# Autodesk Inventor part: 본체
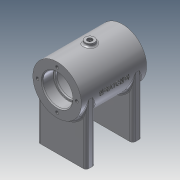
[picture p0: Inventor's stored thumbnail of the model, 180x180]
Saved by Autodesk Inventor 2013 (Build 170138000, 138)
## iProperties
Created: 2020-07
Part Number: 본체
Material: 알루미늄 6061
Document SubType Name: Modeling
Designer: user
Mass: 305.001 g
Surface Area: 360.073 cm^2
Volume: 112.546 cm^3
Density: 2.71 g/cm^3
Author: user
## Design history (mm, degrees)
sketch "스케치1"
  geometry: C1 r 26 at (0, 0); 1 further point
  constraints: 1 centre point, 1 coincident
  dimensions: "d0" = 52 diameter of C1
extrude "돌출1" new body sketch "스케치1" stored distance "d1" = 70; taper "d2" = 0 deg
node "작업 평면1"
sketch "스케치2"
  geometry: L1 (26, 30)-(-26, 30); L2 (-26, 30)-(-26, 20); L3 (-26, 20)-(26, 20); L4 (26, 20)-(26, 30); L5 (26, -20)-(-26, -20); L6 (-26, -20)-(-26, -30); L7 (-26, -30)-(26, -30); L8 (26, -30)-(26, -20); L9 (15, 0)-(-15, 0); 4 further points
  constraints: 18 end point, 4 parallel, 3 midpoint, 3 perpendicular, 2 horizontal, 2 vertical alignment, 1 coincident, 1 other
  dimensions: "d4" = 60 distance between parallel lines of L7 L1; "d6" = 52 distance between parallel lines of L2 L4; "d7" = 10 distance of L1.end L2.end; "d8" = 10 distance of L5.end L6.end; "d9" = 52 distance of L6.end L7.end; "d10" = 30 distance of L9.start L9.end
extrude "돌출2" join sketch "스케치2" stored distance "d11" = 70; taper "d12" = 0 deg
sketch "스케치3"
  geometry: C1 r 26 at (0, 0) reference; C2 r 16 at (0, 0)
  constraints: 1 centre point, 1 coincident
  dimensions: "d13" = 32 diameter of C2
extrude "돌출3" cut sketch "스케치3" distance "d14" = 12; taper "d15" = 0 deg
sketch "스케치4"
  geometry: C1 r 16 at (0, 0) reference; C2 r 14 at (0, 0)
  constraints: 1 centre point, 1 coincident
  dimensions: "d16" = 28 diameter of C2
extrude "돌출4" cut sketch "스케치4" distance "d17" = 2; taper "d18" = 0 deg
sketch "스케치5"
  geometry: C1 r 14 at (0, 0) reference; C2 r 21 at (0, 0)
  constraints: 1 centre point, 1 coincident
  dimensions: "d19" = 42 diameter of C2
extrude "돌출5" cut sketch "스케치5" distance "d20" = 42; taper "d21" = 0 deg
node "작업 평면2"
sketch "스케치6"
  geometry: L1 (0, 0)-(0, -26); L2 (7.182, -19.734)-(9.919, -27.251); L3 (9.919, -27.251)-(15.557, -25.199); L4 (15.557, -25.199)-(12.821, -17.681); L5 (0, 0)-(7.182, -19.734); L6 (12.821, -17.681)-(7.182, -19.734); 2 further points
  constraints: 12 end point, 2 perpendicular, 1 collinear, 1 vertical, 1 vertical alignment, 3 other
  dimensions: "d23" = 6 distance between parallel lines of L4 L2; "d25" = 29 distance from line of point (0, 0) L3; "d26" = 20 deg angle of L5 L1
revolve "회전1" sketch "스케치6" stored, may be unused: angle "d27" = 90 deg
node "작업 평면5"
  node "작업 평면4"
sketch "스케치7"
  geometry: C1 r 5 at (0, 0); 1 further point
  constraints: 1 centre point, 1 coincident
  dimensions: "d29" = 10 diameter of C1
extrude "돌출6" join sketch "스케치7" stored distance "d30" = 42; taper "d31" = 0 deg
sketch "스케치8"
  geometry: C1 r 5 at (0, 0) reference
hole "구멍1" sketch "스케치8" at (0, 0) diameter "d32" = 5.188; stored, may be unused: countersink angle "d36" = 90 deg, drill point angle "d38" = 118 deg; dims "d33" = 6, "d34" = 4, "d35" = 2, "d37" = 13.5
sketch "스케치9"
  geometry: C1 r 6 at (0, 0) reference
hole "구멍2" sketch "스케치9" at (0, 0) diameter "d39" = 5.188; stored, may be unused: countersink angle "d43" = 90 deg, drill point angle "d45" = 118 deg; dims "d40" = 6, "d41" = 4, "d42" = 2, "d44" = 13.5
sketch "스케치10" dims "d46" = 42
  geometry: C1 r 26 at (0, 0) reference; 3 further points
  constraints: 2 coincident, 2 vertical alignment, 2 other
hole "구멍3" sketch "스케치10" at (0, 21) diameter "d47" = 3.242; stored, may be unused: countersink angle "d51" = 90 deg, drill point angle "d53" = 118 deg; dims "d48" = 8, "d49" = 4, "d50" = 2, "d52" = 10
sketch "스케치11"
  geometry: L1 (-26, -30)-(-26, -20) reference; L2 (26, -30)-(-26, -30) reference; L3 (-26, 30)-(26, 30) reference; L4 (-26, 20)-(-26, 30) reference; L5 (26, 20)-(-26, 20) reference; L6 (26, 30)-(26, 20) reference; 6 further points
  constraints: 2 vertical alignment, 1 horizontal alignment, 1 midpoint
  dimensions: "d57" = 5 distance from line of L2 point (-20, -25); "d58" = 5 distance from line of L2 point (20, -25); "d59" = 20 horizontal distance of point (0, 0) point (-20, -25); "d60" = 20 horizontal distance of point (0, 0) point (20, -25); "d63" = 5 distance from line of L3 point (20, 25)
hole "구멍4" sketch "스케치11" at (-20, -25), (20, 25), (-20, 25), (20, -25) diameter "d64" = 4.134; stored, may be unused: countersink angle "d68" = 90 deg, drill point angle "d70" = 118 deg; dims "d65" = 8, "d66" = 4, "d67" = 2, "d69" = 10
chamfer "모따기1" distance "d72" = 1; stored, may be unused: second distance "d73" = 2, angle "d74" = 45 deg
fillet "모깎기2" dims "d75" = 0.3
fillet "모깎기3" dims "d76" = 2
fillet "모깎기4" dims "d77" = 2
fillet "모깎기5" dims "d78" = 3
fillet "모깎기6" dims "d79" = 3
node "작업 평면6"
sketch "스케치12"
  geometry: L1 (-26, -35)-(26, -35) reference; L2 (-29, -5)-(-29, 5) reference; 2 further points
  constraints: 1 other
  dimensions: "d81" = 35 distance from line of L1 point (0, 0); "d82" = 29 distance from line of L2 point (0, 0)
feature "엠보싱1" sketch "스케치12" dims "d2" = 0, "d83" = 0.5, "d84" = 0
node "솔리드1"
mirror "대칭1"
pattern_circular "원형 패턴1" dims angle "d55" = 360 deg
mirror "대칭2"
node "투영된 루프1"
node "절단 모서리 투영1"
other parameters: "d3" = -64, "d28" = 3, "d80" = -71.5
